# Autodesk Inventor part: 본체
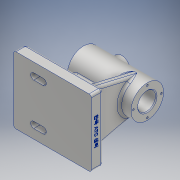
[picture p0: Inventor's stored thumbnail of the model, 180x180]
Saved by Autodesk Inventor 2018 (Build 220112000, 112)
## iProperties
Created: 2022-06
Part Number: 본체
Material: 알루미늄 6061
Document SubType Name: Modeling
Designer: 4강의실
Density: 2.7 g/cm^3
Appearance: 알루미늄 - 평지
Mass: 638.981 g
Surface Area: 521.522 cm^2
Volume: 236.66 cm^3
Author: 4강의실
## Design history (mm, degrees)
sketch "스케치1"
  geometry: L1 (50, -43)-(-50, -43); L2 (-50, -43)-(-50, 43); L3 (-50, 43)-(50, 43); L4 (50, 43)-(50, -43); 1 further point
  constraints: 8 end point, 2 parallel, 1 horizontal, 1 perpendicular
  dimensions: "d0" = 100 distance of L1.start L1.end; "d1" = 86 distance of L1.end L2.end; "d2" = 43 vertical distance of L1.end point (0, 0); "d3" = 50 distance from line of L4 point (0, 0)
extrude "돌출1" new body sketch "스케치1" distance "d4" = 15; taper "d5" = 0 deg
sketch "스케치2"
  geometry: L1 (-59.635, 57)-(61.669, 57); L2 (50, -15)-(-50, -15) reference; L3 (-32, 78)-(-32, 71.5); L4 (-32, 71.5)-(30, 71.5); L5 (30, 71.5)-(30, 68.5); L6 (30, 68.5)-(50, 68.5); L7 (50, 68.5)-(50, 78); L8 (50, 78)-(-32, 78); L9 (50, 0)-(50, -15) reference; 1 further point
  constraints: 14 end point, 5 perpendicular, 1 horizontal, 1 vertical
  dimensions: "d6" = 72 distance between parallel lines of L2 L1; "d7" = 23 diameter of L6 L1; "d8" = 42 diameter of L8 L1; "d9" = 29 diameter of L4 L1; "d10" = 82 distance between parallel lines of L7 L3; "d11" = 0 distance between parallel lines of L9 L7; "d12" = 20 distance of L5.end L6.end
revolve "회전1" sketch "스케치2" stored, may be unused: angle "d13" = 90 deg
node "작업 평면1"
sketch "스케치3"
  geometry: L1 (63.441, 61.814)-(78, 0); L2 (78, 0)-(8, 0); L3 (8, 0)-(22.559, 61.814); L4 (86, 0)-(86, -15) reference; A1 r 21 centre (43, 57) between (63.441, 61.814) and (22.559, 61.814) reference; 2 further points
  constraints: 6 end point, 2 point on circle, 2 tangent, 1 coincident, 1 horizontal, 1 midpoint
  dimensions: "d15" = 8 distance from line of L4 L1.end
extrude "돌출2" join sketch "스케치3" distance "d16" = 10; taper "d17" = 0 deg
sketch "스케치4"
  geometry: L1 (-21.897, 36)-(-35, 0); L2 (-50, 0)-(50, 0) reference; L3 (-50, 0)-(-50, -15) reference; L4 (-32, 36)-(50, 36) reference; 1 further point
  constraints: 2 end point, 2 point on line
  dimensions: "d18" = 15 distance from line of L3 L1.end; "d19" = 70 deg angle of L2 L1
feature "리브1" sketch "스케치4" dims "d20" = 1, "d21" = 10, "d22" = 0, "d23" = 0, "d24" = 1, "d25" = 1
sketch "스케치5"
  geometry: L1 (-24, 27)-(-12, 27); L2 (-24, 34)-(-12, 34); L3 (-12, 20)-(-24, 20); L4 (-50, -43)-(-50, 43) reference; A1 r 7 centre (-24, 27) between (-24, 34) and (-24, 20); A2 r 7 centre (-12, 27) between (-12, 20) and (-12, 34); 2 further points
  constraints: 8 end point, 4 point on circle, 4 tangent, 2 centre point, 1 horizontal, 1 midpoint, 1 parallel
  dimensions: "d26" = 12 distance of L1.end L1.start; "d27" = 26 distance from line of L4 L1.start; "d28" = 27 vertical distance of point (0, 0) L1.start; "d29" = 7 radius of A1
extrude "돌출3" join sketch "스케치5" distance "d30" = 3; taper "d31" = 0 deg
sketch "스케치6"
  geometry: L1 (-24, 27)-(-12, 27); L2 (-24, 23)-(-12, 23); L3 (-12, 31)-(-24, 31); L4 (-50, -43)-(-50, 43) reference; A1 r 4 centre (-24, 27) between (-24, 31) and (-24, 23); A2 r 4 centre (-12, 27) between (-12, 23) and (-12, 31); 2 further points
  constraints: 8 end point, 4 point on circle, 4 tangent, 2 centre point, 1 horizontal, 1 midpoint, 1 parallel
  dimensions: "d32" = 12 distance of L1.start L1.end; "d34" = 27 vertical distance of point (0, 0) point (-18, 27); "d35" = 4 radius of A2; "d36" = 26 distance from line of L4 L1.start
extrude "돌출4" cut sketch "스케치6" extent not by distance; stored distance "d37" = 3; taper "d38" = 0 deg
node "작업 평면2"
sketch "스케치7"
  geometry: L1 (32, 21)-(32, -21) reference; L2 (-50, 43)-(50, 43) reference; C1 r 11 at (7, 0); 1 further point
  constraints: 1 centre point
  dimensions: "d40" = 22 diameter of C1; "d41" = 25 distance from line of L1 C1.centre; "d42" = 43 distance from line of L2 C1.centre
extrude "돌출5" join sketch "스케치7" stored distance "d43" = 3; taper "d44" = 0 deg
sketch "스케치8"
  geometry: C1 r 11 at (7, 0) reference; C2 r 7 at (7, 0); 1 further point
  constraints: 1 centre point, 1 coincident
  dimensions: "d45" = 14 diameter of C2
extrude "돌출6" cut sketch "스케치8" distance "d46" = 4; taper "d47" = 0 deg
sketch "스케치9"
  geometry: C1 r 7 at (0, 0) reference; 1 further point
hole "구멍1" sketch "스케치9" at (0, 0) diameter "d48" = 4.917; stored, may be unused: countersink angle "d52" = 82 deg, drill point angle "d54" = 0 deg; dims "d49" = 12, "d50" = 3.023, "d51" = 2, "d53" = 15
sketch "스케치10"
  geometry: L1 (-43, -57)-(-43, -72) reference; C1 r 21 at (0, 0) reference; 2 further points
  dimensions: "d55" = 43 distance from line of L1 point (0, 18); "d56" = 18 distance of C1.centre point (0, 18)
hole "구멍2" sketch "스케치10" at (0, 18) diameter "d57" = 2.459; stored, may be unused: countersink angle "d61" = 82 deg, drill point angle "d63" = 118 deg; dims "d58" = 8, "d59" = 3.023, "d60" = 2, "d62" = 10
sketch "스케치11"
  geometry: L1 (43, -72)-(-43, -72) reference; L2 (-43, -57)-(-43, -72) reference; 2 further points
  dimensions: "d67" = 90 distance from line of L1 point (0, 18); "d68" = 43 distance from line of L2 point (0, 18)
hole "구멍3" sketch "스케치11" at (0, 18) diameter "d69" = 2.459; stored, may be unused: countersink angle "d73" = 82 deg, drill point angle "d75" = 118 deg; dims "d70" = 8, "d71" = 3.023, "d72" = 2, "d74" = 10
node "작업 평면3"
sketch "스케치12"
  geometry: L1 (86, -15)-(0, -15) reference; L2 (0, 0)-(0, -15) reference; 2 further points
  constraints: 1 other
  dimensions: "d80" = 6 distance from line of L1 point (43, -9); "d81" = 43 distance from line of L2 point (43, -9)
feature "엠보싱1" sketch "스케치12" dims "d0" = 100, "d1" = 86, "d2" = 43, "d3" = 50, "d82" = 0.5, "d83" = 0
chamfer "모따기1" distance "d84" = 1; stored, may be unused: second distance "d85" = 2, angle "d86" = 45 deg
fillet "모깎기2" dims "d88" = 1
fillet "모깎기3" dims "d89" = 3
fillet "모깎기4" dims "d90" = 3
fillet "모깎기5" dims "d91" = 3
fillet "모깎기6" dims "d92" = 3
fillet "모깎기7" dims "d93" = 3
sketch "스케치13"
  geometry: 1 further point
node "솔리드1"
mirror "미러1"
pattern_circular "원형 패턴1" dims angle "d65" = 360 deg
pattern_circular "원형 패턴2" dims angle "d77" = 360 deg
node "투영된 루프1"
other parameters: "d14" = -15, "d39" = 81, "d79" = 38.75
